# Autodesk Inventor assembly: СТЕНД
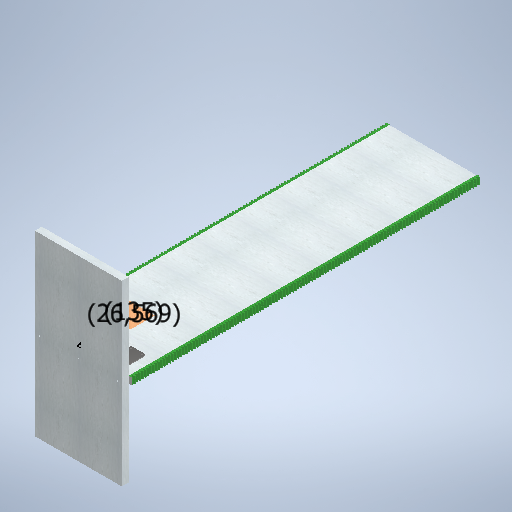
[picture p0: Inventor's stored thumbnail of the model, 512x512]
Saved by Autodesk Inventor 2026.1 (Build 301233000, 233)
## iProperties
Created: 2025-12
Part Number: СТЕНД
Document SubType Name: Assembly
Designer: Yury Melnikov
Author: Yury Melnikov
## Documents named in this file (7)
- C:\Users\user\Documents\Проекты\ВсОШ_РОБО\Стенд\СТЕНД.iam
- C:\Users\user\Documents\Проекты\ВсОШ_РОБО\Стенд\МОДЕЛИ\ЛДСП.ipt
- C:\Users\user\Documents\Проекты\ВсОШ_РОБО\Стенд\МОДЕЛИ\РЕЙКА.ipt
- C:\Users\user\Documents\Проекты\ВсОШ_РОБО\Стенд\МОДЕЛИ\РЕЙКА_MIR.ipt
- C:\Users\user\Documents\Проекты\ВсОШ_РОБО\Стенд\МОДЕЛИ\ЛДСП_НИЗ.ipt
- C:\Users\user\Documents\Проекты\ВсОШ_РОБО\Стенд\МОДЕЛИ\УГОЛОК.ipt
- C:\Users\user\Documents\Проекты\ВсОШ_РОБО\Стенд\МОДЕЛИ\РЕБРО.ipt
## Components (13 placed, 6 different names)
1. ЛДСП:1 — Совмещение:1, Заподлицо:1, Совмещение:2, Заподлицо:2, Совмещение:5, Совмещение:6, Совмещение:7, Совмещение:8, Совмещение:10, Совмещение:13
2. РЕЙКА_MIR:1
3. РЕЙКА_MIR:2
4. РЕЙКА_MIR:3
5. РЕЙКА_MIR:4
6. ЛДСП_НИЗ:1 — Совмещение:5, Совмещение:6, Совмещение:7, Совмещение:9, Совмещение:11, Совмещение:12
7. УГОЛОК:1 — Совмещение:8, Совмещение:9
8. УГОЛОК:2 — Совмещение:10, Совмещение:11
9. РЕБРО:1 — Совмещение:12, Совмещение:13
10. РЕЙКА:1 — Совмещение:1, Заподлицо:1, Совмещение:2
11. РЕЙКА:2
12. РЕЙКА:3
13. РЕЙКА:4
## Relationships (13: Mate 11, Flush 2)
- Совмещение:1 [Mate]: ЛДСП:1 ↔ РЕЙКА:1
- Заподлицо:1 [Flush]: ЛДСП:1 ↔ РЕЙКА:1
- Совмещение:2 [Mate]: ЛДСП:1 ↔ РЕЙКА:1
- Заподлицо:2 [Flush]: ЛДСП:1
- Совмещение:5 [Mate]: ЛДСП:1 ↔ ЛДСП_НИЗ:1
- Совмещение:6 [Mate]: ЛДСП:1 ↔ ЛДСП_НИЗ:1
- Совмещение:7 [Mate]: ЛДСП:1 ↔ ЛДСП_НИЗ:1
- Совмещение:8 [Mate]: ЛДСП:1 ↔ УГОЛОК:1
- Совмещение:9 [Mate]: ЛДСП_НИЗ:1 ↔ УГОЛОК:1
- Совмещение:10 [Mate]: ЛДСП:1 ↔ УГОЛОК:2
- Совмещение:11 [Mate]: ЛДСП_НИЗ:1 ↔ УГОЛОК:2
- Совмещение:12 [Mate]: ЛДСП_НИЗ:1 ↔ РЕБРО:1
- Совмещение:13 [Mate]: ЛДСП:1 ↔ РЕБРО:1
